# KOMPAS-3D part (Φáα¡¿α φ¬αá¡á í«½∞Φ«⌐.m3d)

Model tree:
1. Эскиз:1
2. Операция выдавливания:1
     Расстояние 1 = 0.5
3. Эскиз:2
4. Операция выдавливания:2
     Расстояние 1 = 2.5
5. Эскиз:3
6. Операция выдавливания:3
     Расстояние 1 = 0.5
7. Скругление:1
     Радиус = 1
8. Эскиз:4
9. Операция выдавливания:4
     Расстояние 1 = 8.3
10. Эскиз:5
11. Вырезать элемент выдавливания:1
     Расстояние 1 = 10
12. Эскиз:6
13. Операция выдавливания:5
     Расстояние 1 = 8.3; Расстояние 2 = 1
14. Эскиз:7
15. Операция выдавливания:6
     Расстояние 1 = 0.5; Расстояние 2 = 1
16. Эскиз:8
17. Операция выдавливания:7
     Расстояние 1 = 0.5; Расстояние 2 = 1
18. Скругление:2
     Радиус = 0.5
19. Скругление:3
     Радиус = 0.5
20. Скругление:4
     Радиус = 0.5
21. Скругление:5
     Радиус = 0.5
22. Скругление:6
     Радиус = 0.5
23. Эскиз:9
24. Операция выдавливания:8
     Расстояние 1 = 3.7; Расстояние 2 = 3.7
25. Эскиз:10
26. Вырезать элемент выдавливания:3
     Расстояние 1 = 0.5
27. Эскиз:11
28. Операция выдавливания:9
     Расстояние 1 = 0.5; Расстояние 2 = 3.7
29. Эскиз:12
30. Операция выдавливания:10
     Расстояние 1 = 0.5; Расстояние 2 = 3.7
31. Скругление:7
     Радиус = 0.5
32. Скругление:8
     Радиус = 0.5
33. Скругление:10
     Радиус = 0.1

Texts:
  шарнир экрана большой
  Сплав АЛ8  ГОСТ 1583-93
